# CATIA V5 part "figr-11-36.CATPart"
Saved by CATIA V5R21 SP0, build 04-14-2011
Part number: Part1
Bounding box of the stored display mesh (mm): x -55 to 66, y -170 to 170, z -50 to 0
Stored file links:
  D:\CATIA V5R21 E-RESOURCES\CATIA-V5R21\catia-v5r21-prt\c11-catia-v5r21-prt\c11-catia-v5r21-figr-11-36.CATPart
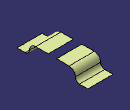
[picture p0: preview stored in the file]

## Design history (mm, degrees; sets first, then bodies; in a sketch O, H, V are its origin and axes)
Set1
  Extrude1: Element1 Sketch1, Lim1 66, Lim2 55, Direction yz-plane
  Symmetry1: ToTransfor Extrude1, Reference zx-plane
Body1 (main body)
  Sketch1 on yz-plane, origin (0, 0, 0), H (0, 1, 0), V (0, 0, 1)
    point P1 (20, 0)
    line L1 (20, 0) -> (80, 0)
    arc A1 centre (80, -30) radius 30 from (80, 0) to (110, -30) cw
    arc A2 centre (130, -30) radius 20 from (110, -30) to (130, -50) ccw
    line L2 (130, -50) -> (170, -50)
    coincidence: P1 H
    horizontal: L1 H
    tangency: A1 L1, A2 A1, L2 A2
